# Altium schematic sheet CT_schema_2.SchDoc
size 591 x 347 mm
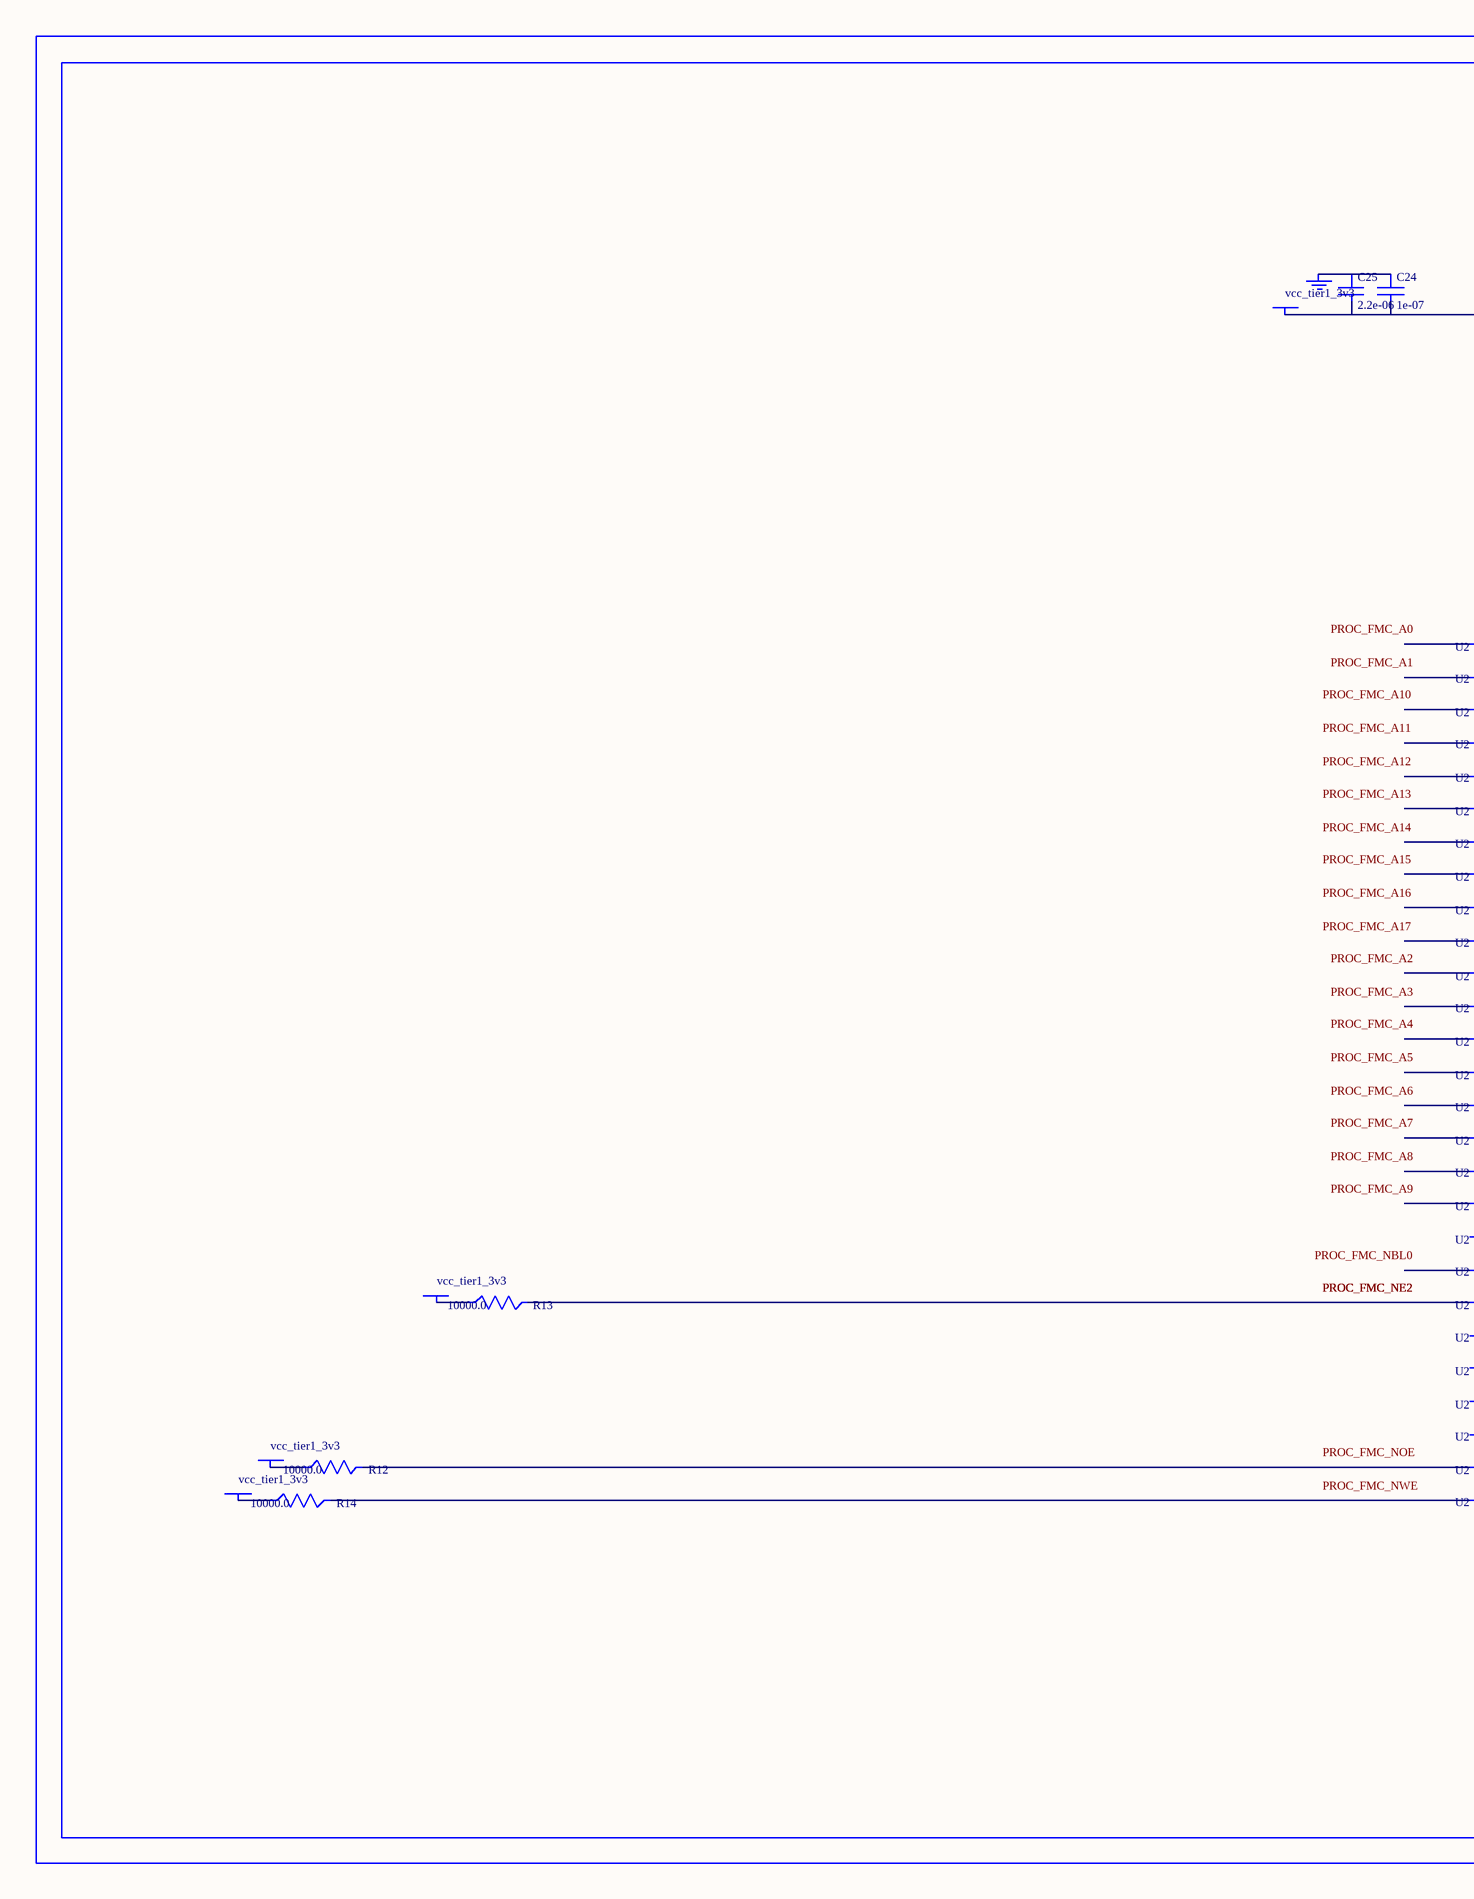
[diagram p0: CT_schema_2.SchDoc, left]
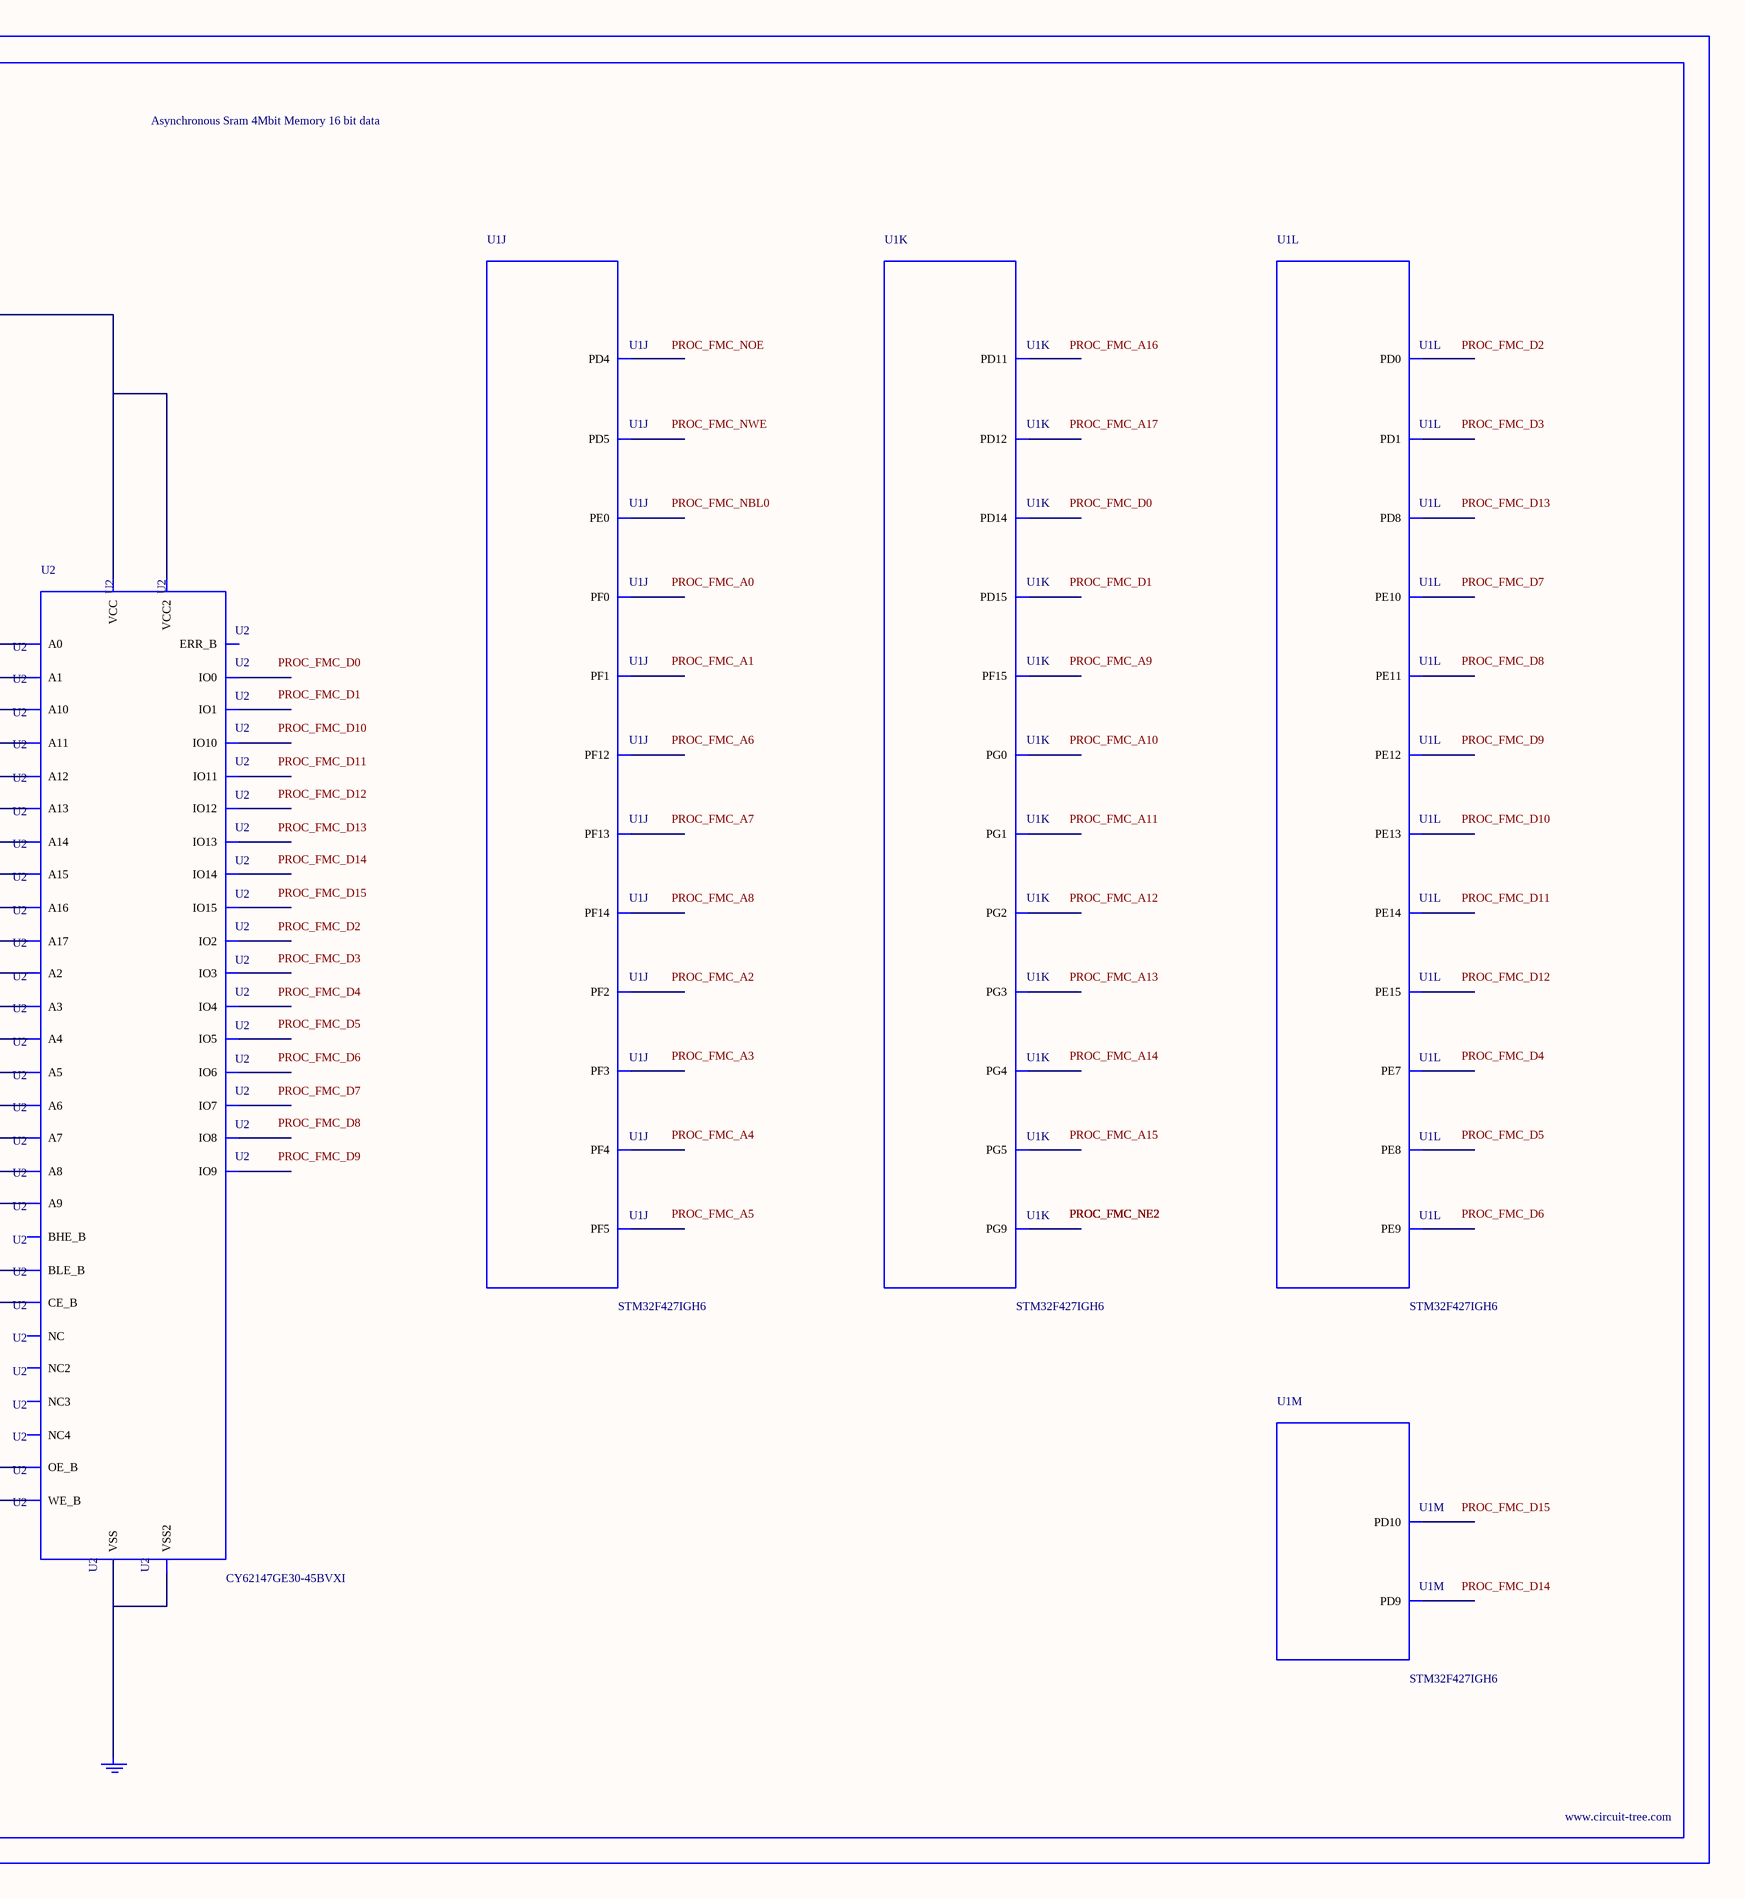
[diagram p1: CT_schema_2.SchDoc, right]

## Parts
BORDER1  (no value)
C24  1e-07  [C0402]
C25  2.2e-06  [C0603]
GND_INSTANCE_1_0  (no value)
GND_INSTANCE_1_1  (no value)
POWER_INSTANCE_1_0  vcc_tier1_3v3
POWER_INSTANCE_1_1  vcc_tier1_3v3
POWER_INSTANCE_1_2  vcc_tier1_3v3
POWER_INSTANCE_1_3  vcc_tier1_3v3
R12  10000.0  [R0603]
R13  10000.0  [R0603]
R14  10000.0  [R0603]
U1  STM32F427IGH6  [UFBGA176_25]  (parts J,K,L,M of 16)
U2  CY62147GE30-45BVXI  [VFBGA48]

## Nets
NetC24_1: C24.1 C25.1 GND_INSTANCE_1_0.0(GND)
NetC24_2: C24.2 C25.2 POWER_INSTANCE_1_0.0(PWR) U2.D6(VCC) U2.E1(VCC2)
NetGND_INSTANCE_1_1_0: GND_INSTANCE_1_1.0(GND) U2.D1(VSS) U2.E6(VSS2)
NetPOWER_INSTANCE_1_1_0: POWER_INSTANCE_1_1.0(PWR) R12.1
NetPOWER_INSTANCE_1_2_0: POWER_INSTANCE_1_2.0(PWR) R13.1
NetPOWER_INSTANCE_1_3_0: POWER_INSTANCE_1_3.0(PWR) R14.1
NetR12_2: R12.2 U2.A2(OE_B)
NetR13_2: R13.2 U2.B5(CE_B)
NetR14_2: R14.2 U2.G5(WE_B)

Not connected (* = marked no-connect by the designer): U1 A4(PE0) B12(PD0) C10(PG9) C11(PD5) C12(PD1) D10(PD4) E2(PF0) H2(PF2) H3(PF1) J2(PF3) J3(PF4) K3(PF5) K13(PG5) K14(PG4) K15(PG3) L14(PD15) L15(PG2) M7(PG1) M14(PD14) N6(PF13) N7(PG0) N11(PE13) N13(PD12) N14(PD11) N15(PD10) P6(PF12) P7(PF15) P8(PE8) P9(PE9) P10(PE11) P11(PE14) P14(PD9) P15(PD8) R7(PF14) R8(PE7) R9(PE10) R10(PE12) R11(PE15); U2 A1(BLE_B) A3(A0) A4(A1) A5(A2) A6(NC) B1(IO8) B2(BHE_B) B3(A3) B4(A4) B6(IO0) C1(IO9) C2(IO10) C3(A5) C4(A6) C5(IO1) C6(IO2) D2(IO11) D3(A17) D4(A7) D5(IO3) E2(IO12) E3(ERR_B) E4(A16) E5(IO4) F1(IO14) F2(IO13) F3(A14) F4(A15) F5(IO5) F6(IO6) G1(IO15) G2(NC2) G3(A12) G4(A13) G6(IO7) H1(NC3) H2(A8) H3(A9) H4(A10) H5(A11) H6(NC4)

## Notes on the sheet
- Labels drawn without touching a wire or pin: PROC_FMC_A0, PROC_FMC_A1, PROC_FMC_A2, PROC_FMC_A3, PROC_FMC_A4, PROC_FMC_A5, PROC_FMC_A6, PROC_FMC_A7, PROC_FMC_A8, PROC_FMC_A9, PROC_FMC_A10, PROC_FMC_A11, PROC_FMC_A12, PROC_FMC_A13, PROC_FMC_A14, PROC_FMC_A15, PROC_FMC_A16, PROC_FMC_A17, PROC_FMC_D0, PROC_FMC_D1, PROC_FMC_D2, PROC_FMC_D3, PROC_FMC_D4, PROC_FMC_D5, PROC_FMC_D6, PROC_FMC_D7, PROC_FMC_D8, PROC_FMC_D9, PROC_FMC_D10, PROC_FMC_D11, PROC_FMC_D12, PROC_FMC_D13, PROC_FMC_D14, PROC_FMC_D15, PROC_FMC_NBL0, PROC_FMC_NOE, PROC_FMC_NWE

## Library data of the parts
BORDER1 = BORDER_PAGE1
C24 = C0402C104K3RACTU
C25 = C0603C225K8RACTU
GND_INSTANCE_1_0 GND_INSTANCE_1_1 = GND
POWER_INSTANCE_1_0-POWER_INSTANCE_1_3 = PWR
R12-R14 = RC0603JR-0710KL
